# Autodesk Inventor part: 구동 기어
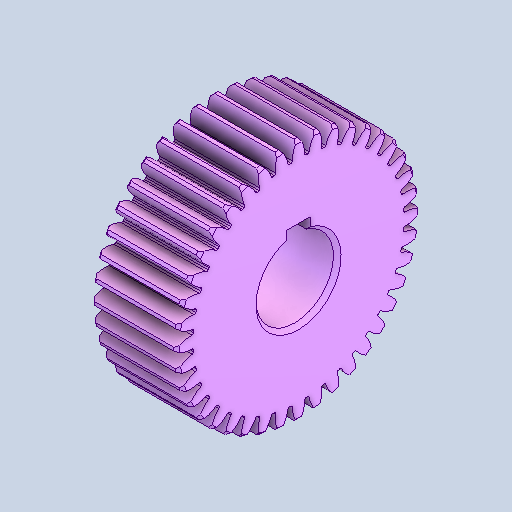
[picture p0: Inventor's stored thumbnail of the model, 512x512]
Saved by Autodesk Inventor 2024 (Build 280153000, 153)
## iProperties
Created: 2025-11
Part Number: 구동 기어
Material: 강철, 합금
Document SubType Name: Modeling
Designer: Eud07
Density: 7.73 g/cm^3
Appearance: 기본값
Author: jhkim
Sending System: Autodesk Inventor 2026
Preprocessor: ST-DEVELOPER v20.1
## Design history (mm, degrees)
node "구동 기어1"
node "솔리드2"
node "솔리드1"
